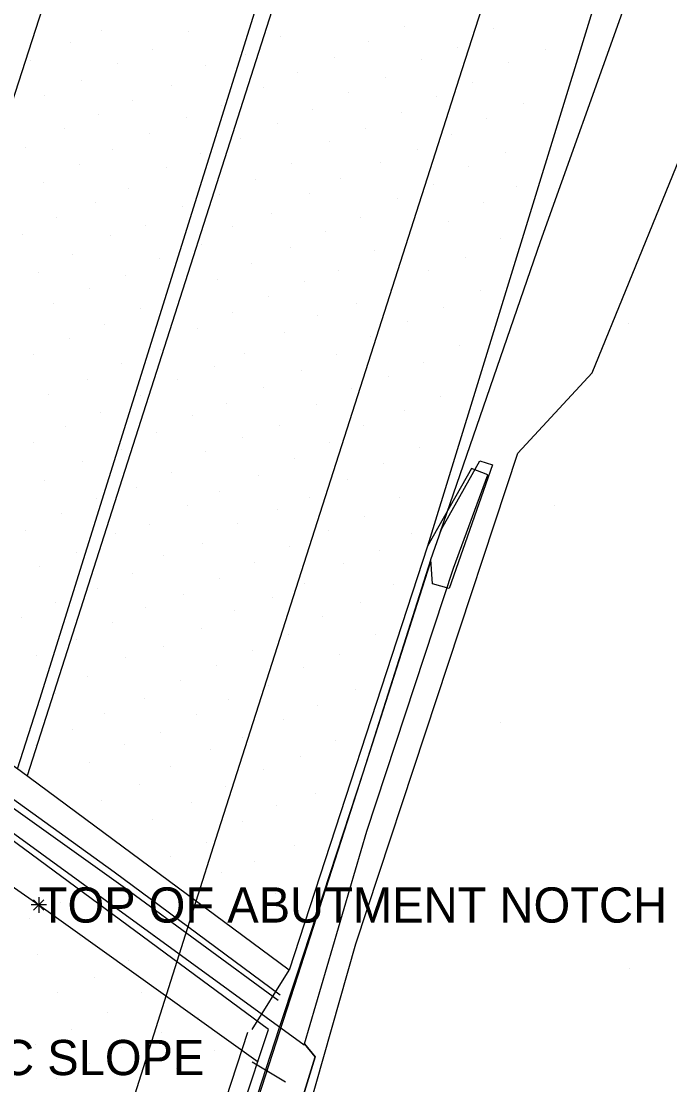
# Model space of a CAD drawing. Extents: x 0 to 1739264, y 0 to 465304.
# Drawn here: x 1738871.3 to 1738904.4, y 464726.9 to 464781.2 of the extents above; entities that cross this region are included whole.
import ezdxf

# ---------------------------------------------------------------- set-up
doc = ezdxf.new("R2010")
doc.units = 0
for name, color, linetype in [('Default', 7, 'Continuous'), ('S_Ground_SpotElevation', 7, 'Continuous'), ('S_Misc_MiscItems', 7, 'Continuous'), ('S_Terrain_Flow_Arrows', 7, 'Continuous'), ('S_Terrain_Holes', 7, 'Continuous'), ('S_Terrain_Imported_Contours', 7, 'Continuous'), ('S_Terrain_Low_Points', 7, 'Continuous'), ('S_Terrain_Major_Contours', 7, 'Continuous'), ('S_Terrain_Major_Contours_Label', 7, 'Continuous'), ('S_Terrain_Minor_Contours', 7, 'Continuous'), ('S_Terrain_Minor_Contours_Label', 7, 'Continuous'), ('S_Terrain_Spots', 7, 'Continuous'), ('S_Terrain_Triangles', 7, 'Continuous'), ('S_Terrain_Voids', 7, 'Continuous'), ('S_Terrain_XSC', 7, 'Continuous'), ('S_Text', 7, 'Continuous')]:
    doc.layers.add(name, color=color, linetype=linetype)

# ---------------------------------------------------------------- blocks, each defined once
blk = doc.blocks.new('POINT_DISPLAY')
at = {"layer": 'Default'}
blk.add_line((0, 0), (0, 0), dxfattribs=at)

msp = doc.modelspace()

# ---------------------------------------------------------------- linework, layer by layer
at = {"layer": 'S_Misc_MiscItems'}
for p, q in [((1738872.440081, 464735.833019), (1738871.915919, 464736.357181)), ((1738872.440081, 464736.357181), (1738871.915919, 464735.833019)), ((1738872.178, 464736.488025), (1738872.178, 464735.702175)), ((1738872.570925, 464736.0951), (1738871.785075, 464736.0951))]:
    msp.add_line(p, q, dxfattribs=at)
at = {"layer": 'S_Terrain_Flow_Arrows'}
msp.add_lwpolyline([(1738892.687, 464755.125694), (1738897.812029, 464769.989389), (1738902.075617, 464781.930598), (1738910.142656, 464804.359585), (1738919.340547, 464832.622766), (1738928.871331, 464862.032838), (1738932.853241, 464874.30507), (1738936.002608, 464878.445083), (1738937.942715, 464881.66331), (1738939.20935, 464884.829898), (1738940.976748, 464890.028993), (1738942.228655, 464893.063026), (1738943.642573, 464895.552112), (1738944.349532, 464896.391626), (1738947.722316, 464897.761359), (1738950.653251, 464898.306307), (1738953.908209, 464898.129567), (1738958.604685, 464897.05826), (1738974.113405, 464893.231793), (1738979.248796, 464891.978924)], dxfattribs=at)
at = {"layer": 'S_Terrain_Holes'}
msp.add_lwpolyline([(1738934.2002, 464881.582801), (1738928.0841, 464866.5372), (1738915.084199, 464825.705001), (1738901.423799, 464784.898002), (1738892.042732, 464754.419656), (1738884.962612, 464732.772667)], dxfattribs=at)
at = {"layer": 'S_Terrain_Imported_Contours'}
for points in [[(1739036.578798, 465290.667492), (1739026.541399, 465259.332012), (1739013.6942, 465219.063488), (1738999.442797, 465174.850323), (1738985.582293, 465132.024273), (1738970.199999, 465085.108929), (1738952.192003, 465029.358624), (1738937.750505, 464984.645672), (1738924.644899, 464943.318829), (1738905.560399, 464884.157001), (1738885.695701, 464823.240203), (1738863.6675, 464755.019294), (1738861.917132, 464749.554455)], [(1738871.099421, 464743.042961), (1738872.2397, 464746.6146), (1738884.148, 464784.717796), (1738894.996801, 464817.751098), (1738911.848199, 464869.926002), (1738930.302797, 464927.737591), (1738944.359194, 464971.624127), (1738958.087007, 465014.085796), (1738974.263903, 465064.602886), (1738992.370806, 465120.419476), (1739017.617296, 465198.443401), (1739037.679499, 465259.797009), (1739046.847902, 465287.700512)], [(1739047.457499, 465287.543713), (1739036.361299, 465253.386303), (1739023.629793, 465214.581799), (1739012.533693, 465180.659283), (1739000.839403, 465144.457989), (1738988.796495, 465107.402325), (1738973.524599, 465060.372296), (1738959.218599, 465015.277325), (1738946.4993, 464976.09959), (1738932.162996, 464931.360577), (1738918.509, 464889.008399), (1738909.080301, 464859.274802), (1738899.9057, 464830.791198), (1738886.617, 464789.705497), (1738873.9013, 464749.930595), (1738871.579396, 464742.691331)], [(1738880.224773, 464736.284008), (1738881.2288, 464739.449607), (1738893.811099, 464778.771506), (1738907.7459, 464822.0036), (1738924.2609, 464872.5013), (1738939.901598, 464921.282574), (1738960.695803, 464986.497418), (1738980.188906, 465046.965923), (1739002.893496, 465116.574383), (1739021.976305, 465176.353375), (1739041.488497, 465235.866894), (1739057.407396, 465284.356213)], [(1738816.833754, 464540.526168), (1738828.844899, 464576.996803), (1738841.383399, 464615.664314), (1738851.1298, 464645.487891), (1738867.0642, 464694.79), (1738880.224773, 464736.284008)]]:
    msp.add_lwpolyline(points, dxfattribs=at)
at = {"layer": 'S_Terrain_Low_Points'}
msp.add_line((1738883.072, 464728.0783), (1738884.783, 464727.058906), dxfattribs=at)
for points in [[(1738853.3716, 464749.177695), (1738858.5024, 464745.655708), (1738872.1784, 464736.0951), (1738883.3875, 464728.0783)], [(1738882.8352, 464729.589896), (1738865.96384, 464677.988066), (1738852.7233, 464636.911414), (1738851.7415, 464633.401588)], [(1738885.748688, 464729.001744), (1738886.292251, 464728.345413), (1738883.4181, 464718.991294), (1738880.4518, 464706.388297), (1738878.8439, 464702.915), (1738876.083852, 464697.452527)]]:
    msp.add_lwpolyline(points, dxfattribs=at)
at = {"layer": 'S_Terrain_Major_Contours'}
msp.add_lwpolyline([(1738892.29817, 464752.489512), (1738892.200972, 464753.74093), (1738892.747708, 464755.29609), (1738894.703808, 464758.7709), (1738895.359891, 464758.576505), (1738893.148648, 464752.258668), (1738892.29817, 464752.489512)], dxfattribs=at)
at = {"layer": 'S_Terrain_Major_Contours_Label'}
for points in [[(1738892.1751, 464753.577796), (1738889.360016, 464744.780725), (1738885.395159, 464732.452095)], [(1738885.395159, 464732.452095), (1738884.2943, 464729.028999), (1738875.3401, 464701.327995), (1738857.6966, 464646.653999), (1738844.752799, 464606.659614), (1738829.9694, 464560.926002), (1738822.141572, 464536.77828)]]:
    msp.add_lwpolyline(points, dxfattribs=at)
at = {"layer": 'S_Terrain_Minor_Contours'}
msp.add_line((1738866.688, 464677.65191), (1738883.905735, 464729.730556), dxfattribs=at)
at = {"layer": 'S_Terrain_Minor_Contours_Label'}
msp.add_line((1738883.072, 464729.730556), (1738884.962612, 464732.772667), dxfattribs=at)
for points in [[(1738884.962612, 464732.772667), (1738871.227336, 464742.952252), (1738856.840841, 464753.154236)], [(1738884.962612, 464732.772667), (1738871.227336, 464742.952252), (1738856.840841, 464753.154236)], [(1738884.516023, 464731.481904), (1738876.0371, 464737.769508), (1738865.0884, 464745.6603), (1738856.423663, 464751.656029)], [(1738884.41171, 464731.223421), (1738876.6018, 464736.9374), (1738870.772589, 464741.112098), (1738861.763167, 464747.609825), (1738856.295528, 464751.38051)], [(1738883.905735, 464729.730556), (1738870.2911, 464739.801795), (1738855.882145, 464750.170609)]]:
    msp.add_lwpolyline(points, dxfattribs=at)
at = {"layer": 'S_Terrain_Spots'}
msp.add_lwpolyline([(1738876.083852, 464697.452527), (1738880.4518, 464706.388297), (1738883.4181, 464718.991294), (1738886.292251, 464728.345413), (1738885.754413, 464729.003456)], dxfattribs=at)
at = {"layer": 'S_Terrain_Triangles'}
for points in [[(1738892.1816, 464753.697898), (1738888.747806, 464742.87814), (1738885.339743, 464732.493165)], [(1738885.339743, 464732.493165), (1738884.4636, 464729.823402), (1738878.6737, 464712.005698), (1738871.4064, 464689.647605), (1738862.8085, 464662.946113), (1738850.8758, 464625.801398), (1738841.409499, 464596.833595), (1738830.533101, 464562.882606), (1738822.877599, 464539.516792), (1738822.019587, 464536.864414)]]:
    msp.add_lwpolyline(points, dxfattribs=at)
at = {"layer": 'S_Terrain_Voids'}
msp.add_lwpolyline([(1739013.416204, 464694.269599), (1738992.965101, 464701.439201), (1738965.663099, 464709.157493), (1738950.283803, 464712.266593), (1738937.222402, 464707.762901), (1738926.393098, 464697.901405), (1738919.4708, 464694.428107), (1738904.882501, 464698.625404), (1738896.325099, 464704.816901), (1738890.220901, 464710.206306), (1738887.592599, 464712.305305), (1738885.2014, 464712.349006), (1738883.3513, 464713.029807), (1738883.0827, 464715.465797), (1738888.3805, 464734.110099), (1738896.6555, 464759.168403), (1738900.4475, 464763.281593), (1738908.0099, 464781.7947), (1738922.6662, 464824.5549), (1738935.930204, 464865.3283), (1738941.605104, 464883.875591)], dxfattribs=at)
at = {"layer": 'S_Terrain_XSC'}
for points in [[(1738888.932599, 464739.860603), (1738893.371499, 464753.302695), (1738895.111751, 464758.061192), (1738894.275673, 464758.382065), (1738892.042732, 464754.419656)], [(1738854.163956, 464751.555463), (1738870.399814, 464740.113374), (1738885.731746, 464728.946791), (1738885.754413, 464729.003456), (1738888.932599, 464739.860603)]]:
    msp.add_lwpolyline(points, dxfattribs=at)

# ---------------------------------------------------------------- block references
at = {"layer": 'S_Ground_SpotElevation'}
for p in [(1738890.839198, 464780.96569), (1738895.400005, 464780.87072), (1738875.386104, 464780.76458), (1738879.820308, 464780.708671), (1738884.540797, 464780.434685), (1738873.776393, 464780.152519), (1738878.0106, 464779.775566), (1738889.044307, 464780.182182), (1738893.550899, 464779.880791), (1738898.058208, 464779.763481), (1738871.742305, 464779.242302), (1738882.733607, 464779.519707), (1738887.301997, 464779.392082), (1738891.7308, 464779.289482), (1738876.199504, 464779.092766), (1738880.682994, 464778.99572), (1738896.1813, 464779.120903), (1738874.348201, 464778.194084), (1738885.417201, 464778.617973), (1738889.873607, 464778.380363), (1738894.350993, 464778.091606), (1738878.967799, 464777.946709), (1738883.638301, 464777.867119), (1738887.989207, 464777.575493), (1738872.493693, 464777.46038), (1738876.966197, 464777.186088), (1738892.473506, 464777.374687), (1738896.914699, 464777.024895), (1738875.205501, 464776.487297), (1738881.514995, 464776.952812), (1738886.167506, 464776.717766), (1738890.7205, 464776.574699), (1738879.728099, 464776.332268), (1738884.3921, 464775.994682), (1738895.063502, 464776.239372), (1738873.501796, 464775.755485), (1738877.812495, 464775.477775), (1738888.884807, 464775.728508), (1738893.251704, 464775.433403), (1738882.490199, 464775.225578), (1738887.029002, 464775.074516), (1738871.504207, 464774.785393), (1738875.968898, 464774.656486), (1738880.445399, 464774.486809), (1738891.499202, 464774.661613), (1738896.000697, 464774.528007), (1738874.247203, 464773.895988), (1738878.699199, 464773.736015), (1738885.072597, 464773.987785), (1738889.649898, 464774.011406), (1738894.130305, 464773.794182), (1738887.569102, 464773.216972), (1738872.421703, 464773.017204), (1738876.753398, 464772.695976), (1738883.256206, 464773.171684), (1738892.327602, 464772.87249), (1738896.593196, 464772.808464), (1738881.407405, 464772.375297), (1738886.007503, 464772.444084), (1738890.493495, 464772.20208), (1738875.058604, 464771.960197), (1738879.532893, 464771.774406), (1738894.918101, 464771.99572), (1738873.103999, 464771.22039), (1738884.073405, 464771.396294), (1738888.621608, 464771.188591), (1738877.618205, 464770.783623), (1738882.093898, 464770.742119), (1738886.818507, 464770.494011), (1738893.0908, 464770.984184), (1738871.342906, 464770.330803), (1738875.864802, 464770.297172), (1738891.155299, 464770.395866), (1738895.748897, 464770.123772), (1738880.516399, 464769.805595), (1738885.015208, 464769.665092), (1738889.3101, 464769.537468), (1738873.882198, 464769.33007), (1738878.359294, 464769.133903), (1738893.950603, 464769.182365), (1738872.168101, 464768.422966), (1738883.027904, 464768.84008), (1738887.509395, 464768.499016), (1738892.090007, 464768.49279), (1738876.614802, 464768.247368), (1738881.332698, 464768.059807), (1738885.776103, 464767.947014), (1738874.781795, 464767.593498), (1738879.428004, 464767.315788), (1738890.151805, 464767.549675), (1738894.732707, 464767.483574), (1738872.929698, 464766.838982), (1738883.906901, 464767.172905), (1738888.419994, 464766.812919), (1738877.352595, 464766.583305), (1738882.092097, 464766.361198), (1738886.435405, 464766.206291), (1738892.857799, 464766.612968), (1738875.518001, 464765.761467), (1738891.020503, 464765.908073), (1738902.287995, 464765.803875), (1738880.264094, 464765.559379), (1738884.753001, 464765.356682), (1738889.142497, 464765.138115), (1738873.766505, 464765.011101), (1738893.677104, 464764.679985), (1738871.925105, 464764.221306), (1738878.419398, 464764.489067), (1738882.708507, 464764.251518), (1738887.407802, 464764.218071), (1738876.417003, 464763.747917), (1738881.137401, 464763.592216), (1738891.838603, 464763.820305), (1738874.670802, 464762.950676), (1738879.2429, 464762.95208), (1738885.592006, 464763.387321), (1738890.060802, 464763.073723), (1738883.666499, 464762.530266), (1738888.167308, 464762.496879), (1738872.652293, 464762.163505), (1738877.395793, 464762.119865), (1738892.682506, 464762.067192), (1738875.320705, 464761.262871), (1738881.763499, 464761.711418), (1738886.385799, 464761.661491), (1738890.848003, 464761.366875), (1738880.021495, 464761.071464), (1738873.538005, 464760.529472), (1738878.175502, 464760.235588), (1738884.496196, 464760.587089), (1738888.769405, 464760.602714), (1738871.911693, 464759.717094), (1738882.605205, 464759.961784), (1738887.029506, 464759.723015), (1738876.381908, 464759.376396), (1738880.712794, 464759.237785), (1738891.647594, 464759.463982), (1738874.4024, 464758.751274), (1738885.2615, 464758.914604), (1738889.790202, 464758.656975), (1738878.965297, 464758.202385), (1738883.424998, 464758.03228), (1738872.475093, 464757.790275), (1738887.969798, 464757.843376), (1738877.191493, 464757.405266), (1738881.426005, 464757.205192), (1738885.999507, 464756.926384), (1738890.622707, 464756.915275), (1738875.104396, 464756.859794), (1738879.798198, 464756.489067), (1738898.515199, 464756.504376), (1738873.329799, 464756.102775), (1738884.370708, 464756.316582), (1738888.793498, 464755.94738), (1738877.846995, 464755.545586), (1738882.311107, 464755.556572), (1738871.494594, 464755.22509), (1738876.1132, 464755.074699), (1738886.966594, 464755.21331), (1738891.194896, 464755.078789), (1738880.539195, 464754.546623), (1738884.961406, 464754.422905), (1738889.568797, 464754.200981), (1738874.130702, 464754.077202), (1738878.537807, 464753.946098), (1738872.210506, 464753.360893), (1738883.210506, 464753.581108), (1738887.749507, 464753.536674), (1738876.984096, 464753.045769), (1738881.431499, 464752.75811), (1738875.200694, 464752.261101), (1738885.747203, 464752.504021), (1738890.314006, 464752.484917), (1738873.022395, 464751.544975), (1738879.577907, 464751.934685), (1738884.107204, 464751.812065), (1738888.611308, 464751.567619), (1738877.650096, 464751.290764), (1738882.158198, 464751.136406), (1738871.290202, 464750.790092), (1738875.921306, 464750.5205), (1738886.688808, 464750.841789), (1738880.4864, 464750.23687), (1738884.926601, 464749.918266), (1738889.363902, 464749.893486), (1738874.108699, 464749.64312), (1738878.572902, 464749.305412), (1738872.068202, 464748.831413), (1738883.090694, 464749.088188), (1738887.564296, 464748.905815), (1738876.598506, 464748.734489), (1738881.246501, 464748.32299), (1738885.702708, 464748.243217), (1738874.643596, 464747.768608), (1738879.434001, 464747.553703), (1738883.896999, 464747.324516), (1738873.051204, 464746.882805), (1738877.561397, 464746.617302), (1738881.870402, 464746.603081), (1738888.3502, 464747.098869), (1738886.439006, 464746.305717), (1738875.539806, 464745.856499), (1738880.2597, 464745.816399), (1738884.696193, 464745.568596), (1738873.921397, 464745.037285), (1738895.788194, 464745.421124), (1738878.373897, 464744.894096), (1738882.610698, 464744.643364), (1738887.344096, 464744.484367), (1738871.995998, 464744.247307), (1738876.534602, 464744.292778), (1738880.951701, 464744.024773), (1738874.778697, 464743.366386), (1738885.523402, 464743.66082), (1738878.927302, 464743.159172), (1738883.669994, 464743.016289), (1738877.333003, 464742.260612), (1738881.707103, 464742.166008), (1738886.324306, 464741.794487), (1738875.387508, 464741.427605), (1738880.000606, 464741.347282), (1738884.334407, 464741.165581), (1738877.983806, 464740.461418), (1738882.585597, 464740.382866), (1738880.725505, 464739.271294), (1738885.262096, 464739.146721), (1738878.915706, 464738.555778), (1738883.187602, 464738.314995), (1738881.504298, 464737.761223), (1738884.255794, 464736.692192), (1738873.264796, 464736.208), (1738890.795396, 464735.861309), (1738871.689906, 464735.418571), (1738874.327907, 464734.414604), (1738872.130595, 464733.573967), (1738876.737407, 464733.282768), (1738902.350007, 464732.862225), (1738875.049693, 464732.411919), (1738873.156795, 464731.635612), (1738877.415599, 464731.619804), (1738875.715602, 464730.587822), (1738880.330104, 464730.360771), (1738873.861598, 464729.758171), (1738878.437099, 464729.602409), (1738872.035792, 464728.988823), (1738876.397105, 464728.825798), (1738881.145106, 464728.643181), (1738874.767604, 464727.993767), (1738879.207194, 464727.76757), (1738873.079005, 464727.224296), (1738877.257594, 464727.060173)]:
    msp.add_blockref('POINT_DISPLAY', p, dxfattribs=at)

# ---------------------------------------------------------------- texts
at = {"layer": 'S_Text'}
for s, p in [('TOP OF ABUTMENT NOTCH', (1738872.178, 464735.1951)), ('CONC SLOPE', (1738864.856, 464727.4044))]:
    msp.add_text(s, height=1.8, dxfattribs=at).set_placement(p)

doc.saveas('drawing.dxf')
